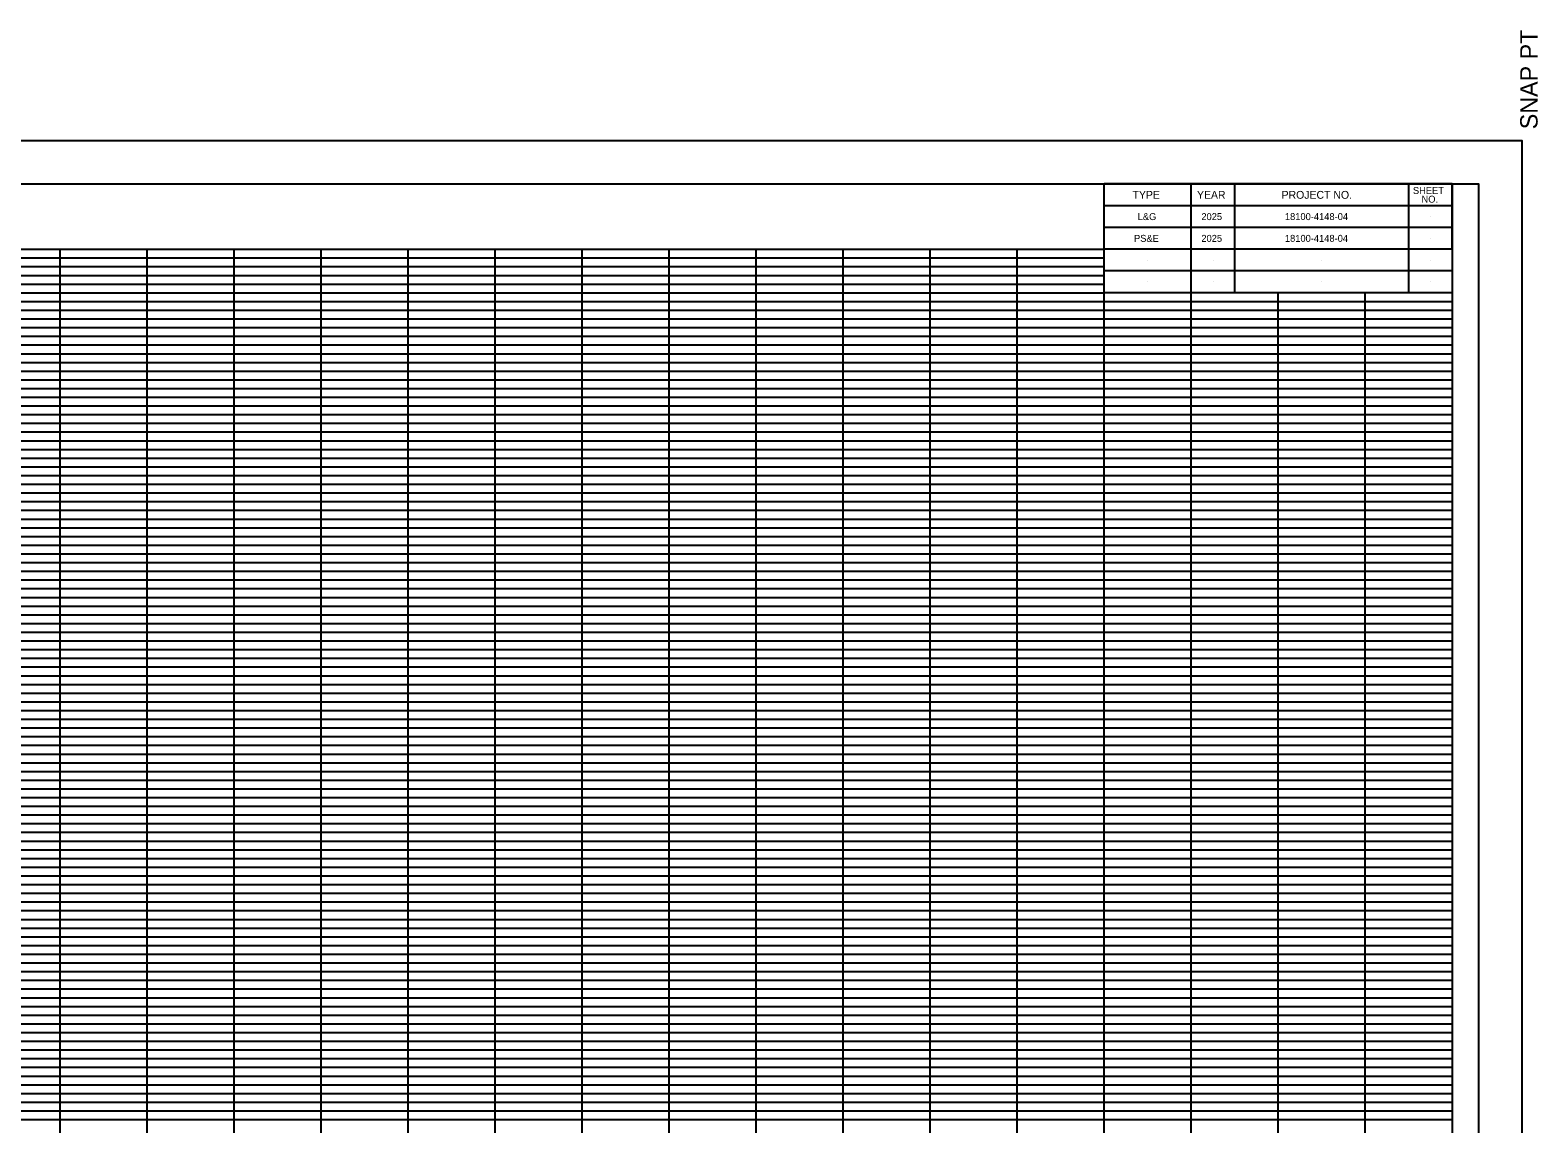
# Model space of a CAD drawing. Extents: x 857 to 1201, y -647 to -396.
import ezdxf

# ---------------------------------------------------------------- set-up
doc = ezdxf.new("R2010")
doc.units = 0
for name, color, linetype in [('DESIGN - SCRATCH - User 1', 7, 'Continuous'), ('DESIGN - SHEET - Corner Text', 7, 'Continuous'), ('DESIGN - SHEET - Light Grid', 7, 'Continuous'), ('DESIGN - SHEET - Linework', 7, 'Continuous'), ('DESIGN - SHEET - Plot Shape', 7, 'Continuous')]:
    doc.layers.add(name, color=color, linetype=linetype)

msp = doc.modelspace()

# ---------------------------------------------------------------- linework, layer by layer
at = {"layer": 'DESIGN - SCRATCH - User 1'}
for p, q in [((1155.97, -417.78), (1155.97, -417.78)), ((1163.47, -417.78), (1163.47, -417.78)), ((1175.97, -417.78), (1175.97, -417.78)), ((1188.47, -417.78), (1188.47, -417.78)), ((1155.97, -420.28), (1155.97, -420.28)), ((1163.47, -420.28), (1163.47, -420.28)), ((1175.97, -420.28), (1175.97, -420.28)), ((1188.47, -420.28), (1188.47, -420.28)), ((1155.97, -422.78), (1155.97, -422.78)), ((1163.47, -422.78), (1163.47, -422.78)), ((1175.97, -422.78), (1175.97, -422.78)), ((1188.47, -422.78), (1188.47, -422.78)), ((1155.97, -425.28), (1155.97, -425.28)), ((1163.47, -425.28), (1163.47, -425.28)), ((1175.97, -425.28), (1175.97, -425.28)), ((1188.47, -425.28), (1188.47, -425.28))]:
    msp.add_line(p, q, dxfattribs=at)
at = {"layer": 'DESIGN - SHEET - Light Grid'}
for p, q in [((870.97, -422.53), (1150.97, -422.53)), ((870.97, -423.53), (1150.97, -423.53)), ((870.97, -424.53), (1150.97, -424.53)), ((870.97, -425.53), (1150.97, -425.53)), ((870.97, -426.53), (1150.97, -426.53)), ((870.97, -427.53), (1190.97, -427.53)), ((870.97, -428.53), (1190.97, -428.53)), ((870.97, -429.53), (1190.97, -429.53)), ((870.97, -430.53), (1190.97, -430.53)), ((870.97, -432.53), (1190.97, -432.53)), ((870.97, -433.53), (1190.97, -433.53)), ((870.97, -434.53), (1190.97, -434.53)), ((870.97, -435.53), (1190.97, -435.53)), ((870.97, -436.53), (1190.97, -436.53)), ((870.97, -437.53), (1190.97, -437.53)), ((870.97, -438.53), (1190.97, -438.53)), ((870.97, -439.53), (1190.97, -439.53)), ((870.97, -440.53), (1190.97, -440.53)), ((870.97, -442.53), (1190.97, -442.53)), ((870.97, -443.53), (1190.97, -443.53)), ((870.97, -444.53), (1190.97, -444.53)), ((870.97, -445.53), (1190.97, -445.53)), ((870.97, -446.53), (1190.97, -446.53)), ((870.97, -447.53), (1190.97, -447.53)), ((870.97, -448.53), (1190.97, -448.53)), ((870.97, -449.53), (1190.97, -449.53)), ((870.97, -450.53), (1190.97, -450.53)), ((870.97, -452.53), (1190.97, -452.53)), ((870.97, -453.53), (1190.97, -453.53)), ((870.97, -454.53), (1190.97, -454.53)), ((870.97, -455.53), (1190.97, -455.53)), ((870.97, -456.53), (1190.97, -456.53)), ((870.97, -457.53), (1190.97, -457.53)), ((870.97, -458.53), (1190.97, -458.53)), ((870.97, -459.53), (1190.97, -459.53)), ((870.97, -460.53), (1190.97, -460.53)), ((870.97, -462.53), (1190.97, -462.53)), ((870.97, -463.53), (1190.97, -463.53)), ((870.97, -464.53), (1190.97, -464.53)), ((870.97, -465.53), (1190.97, -465.53)), ((870.97, -466.53), (1190.97, -466.53)), ((870.97, -467.53), (1190.97, -467.53)), ((870.97, -468.53), (1190.97, -468.53)), ((870.97, -469.53), (1190.97, -469.53)), ((870.97, -470.53), (1190.97, -470.53)), ((870.97, -472.53), (1190.97, -472.53)), ((870.97, -473.53), (1190.97, -473.53)), ((870.97, -474.53), (1190.97, -474.53)), ((870.97, -475.53), (1190.97, -475.53)), ((870.97, -476.53), (1190.97, -476.53)), ((870.97, -477.53), (1190.97, -477.53)), ((870.97, -478.53), (1190.97, -478.53)), ((870.97, -479.53), (1190.97, -479.53)), ((870.97, -480.53), (1190.97, -480.53)), ((870.97, -482.53), (1190.97, -482.53)), ((870.97, -483.53), (1190.97, -483.53)), ((870.97, -484.53), (1190.97, -484.53)), ((870.97, -485.53), (1190.97, -485.53)), ((870.97, -486.53), (1190.97, -486.53)), ((870.97, -487.53), (1190.97, -487.53)), ((870.97, -488.53), (1190.97, -488.53)), ((870.97, -489.53), (1190.97, -489.53)), ((870.97, -490.53), (1190.97, -490.53)), ((870.97, -492.53), (1190.97, -492.53)), ((870.97, -493.53), (1190.97, -493.53)), ((870.97, -494.53), (1190.97, -494.53)), ((870.97, -495.53), (1190.97, -495.53)), ((870.97, -496.53), (1190.97, -496.53)), ((870.97, -497.53), (1190.97, -497.53)), ((870.97, -498.53), (1190.97, -498.53)), ((870.97, -499.53), (1190.97, -499.53)), ((870.97, -500.53), (1190.97, -500.53)), ((870.97, -502.53), (1190.97, -502.53)), ((870.97, -503.53), (1190.97, -503.53)), ((870.97, -504.53), (1190.97, -504.53)), ((870.97, -505.53), (1190.97, -505.53)), ((870.97, -506.53), (1190.97, -506.53)), ((870.97, -507.53), (1190.97, -507.53)), ((870.97, -508.53), (1190.97, -508.53)), ((870.97, -509.53), (1190.97, -509.53)), ((870.97, -510.53), (1190.97, -510.53)), ((870.97, -512.53), (1190.97, -512.53)), ((870.97, -513.53), (1190.97, -513.53)), ((870.97, -514.53), (1190.97, -514.53)), ((870.97, -515.53), (1190.97, -515.53)), ((870.97, -516.53), (1190.97, -516.53)), ((870.97, -517.53), (1190.97, -517.53)), ((870.97, -518.53), (1190.97, -518.53)), ((870.97, -519.53), (1190.97, -519.53)), ((870.97, -520.53), (1190.97, -520.53))]:
    msp.add_line(p, q, dxfattribs=at)
at = {"layer": 'DESIGN - SHEET - Linework'}
for p, q in [((1190.97, -414.03), (1150.97, -414.03)), ((1150.97, -421.53), (1150.97, -414.03)), ((1160.97, -426.53), (1160.97, -414.03)), ((1165.97, -426.53), (1165.97, -414.03)), ((1185.97, -426.53), (1185.97, -414.03)), ((1190.97, -421.53), (1190.97, -414.03)), ((1190.97, -416.53), (1150.97, -416.53)), ((1190.97, -419.03), (1150.97, -419.03)), ((870.97, -421.53), (1150.97, -421.53)), ((1030.97, -621.53), (1030.97, -421.53)), ((1040.97, -621.53), (1040.97, -421.53)), ((1050.97, -621.53), (1050.97, -421.53)), ((1060.97, -621.53), (1060.97, -421.53)), ((1070.97, -621.53), (1070.97, -421.53)), ((1080.97, -621.53), (1080.97, -421.53)), ((1090.97, -621.53), (1090.97, -421.53)), ((1100.97, -621.53), (1100.97, -421.53)), ((1110.97, -621.53), (1110.97, -421.53)), ((1120.97, -621.53), (1120.97, -421.53)), ((1130.97, -621.53), (1130.97, -421.53)), ((1140.97, -621.53), (1140.97, -421.53)), ((1150.97, -621.53), (1150.97, -421.53)), ((1190.97, -421.53), (1150.97, -421.53)), ((1190.97, -424.03), (1150.97, -424.03)), ((1190.97, -426.53), (1150.97, -426.53)), ((1160.97, -621.53), (1160.97, -426.53)), ((1170.97, -621.53), (1170.97, -426.53)), ((1180.97, -621.53), (1180.97, -426.53)), ((870.97, -431.53), (1190.97, -431.53)), ((870.97, -441.53), (1190.97, -441.53)), ((870.97, -451.53), (1190.97, -451.53)), ((870.97, -461.53), (1190.97, -461.53)), ((870.97, -471.53), (1190.97, -471.53)), ((870.97, -481.53), (1190.97, -481.53)), ((870.97, -491.53), (1190.97, -491.53)), ((870.97, -501.53), (1190.97, -501.53)), ((870.97, -511.53), (1190.97, -511.53)), ((870.97, -521.53), (1190.97, -521.53))]:
    msp.add_line(p, q, dxfattribs=at)
for points in [[(858.97, -409.03), (1198.97, -409.03), (1198.97, -629.03), (858.97, -629.03)], [(870.97, -414.03), (1190.97, -414.03), (1190.97, -624.03), (870.97, -624.03)]]:
    msp.add_lwpolyline(points, close=True, dxfattribs=at)
at = {"layer": 'DESIGN - SHEET - Plot Shape'}
msp.add_lwpolyline([(863.97, -414.03), (1193.97, -414.03), (1193.97, -624.03), (863.97, -624.03)], close=True, dxfattribs=at)

# ---------------------------------------------------------------- texts
at = {"layer": 'DESIGN - SHEET - Corner Text'}
msp.add_text('  SNAP PT', height=2, rotation=90, dxfattribs=at).set_placement((1200.77, -409.23))
for s, p in [('L&G', (1154.81, -418.18)), ('2025', (1162.13, -418.18)), ('18100-4148-04', (1171.73, -418.18)), ('PS&E', (1154.39, -420.68)), ('2025', (1162.13, -420.68)), ('18100-4148-04', (1171.73, -420.68))]:
    msp.add_text(s, height=0.8, dxfattribs=at).set_placement(p)
at = {"layer": 'DESIGN - SHEET - Light Grid'}
for s, height, p in [('TYPE', 0.9, (1154.22, -415.73)), ('YEAR', 0.9, (1161.63, -415.73)), ('PROJECT NO.', 0.9, (1171.35, -415.73)), ('SHEET', 0.8, (1186.44, -415.18)), ('NO.', 0.8, (1187.43, -416.18))]:
    msp.add_text(s, height=height, dxfattribs=at).set_placement(p)

doc.saveas('drawing.dxf')
